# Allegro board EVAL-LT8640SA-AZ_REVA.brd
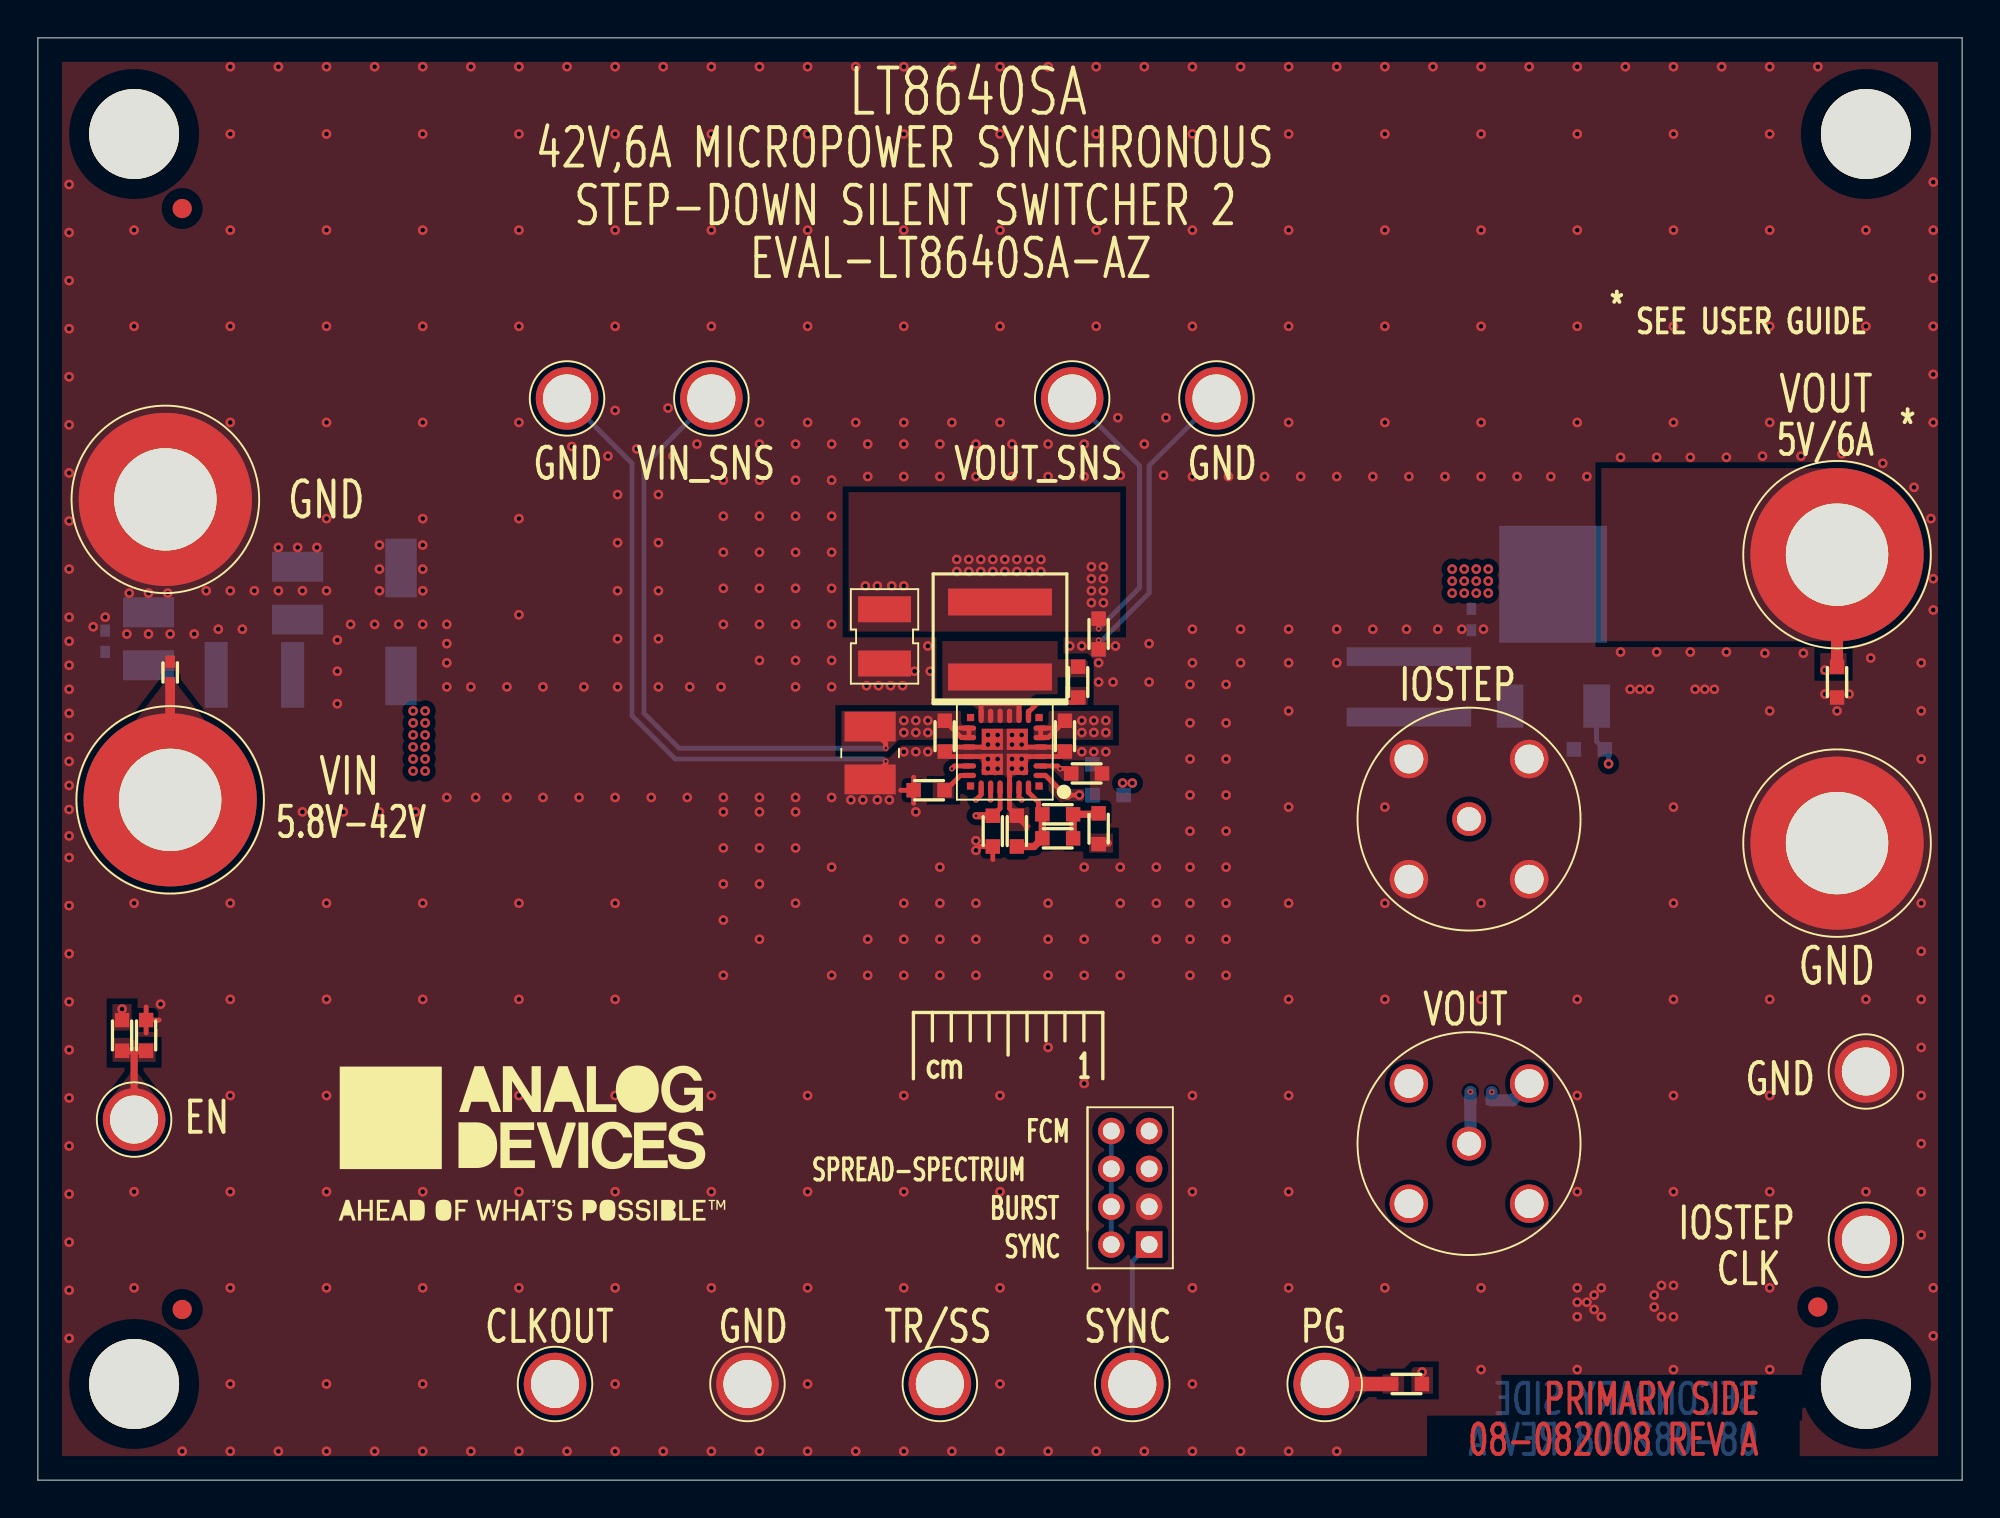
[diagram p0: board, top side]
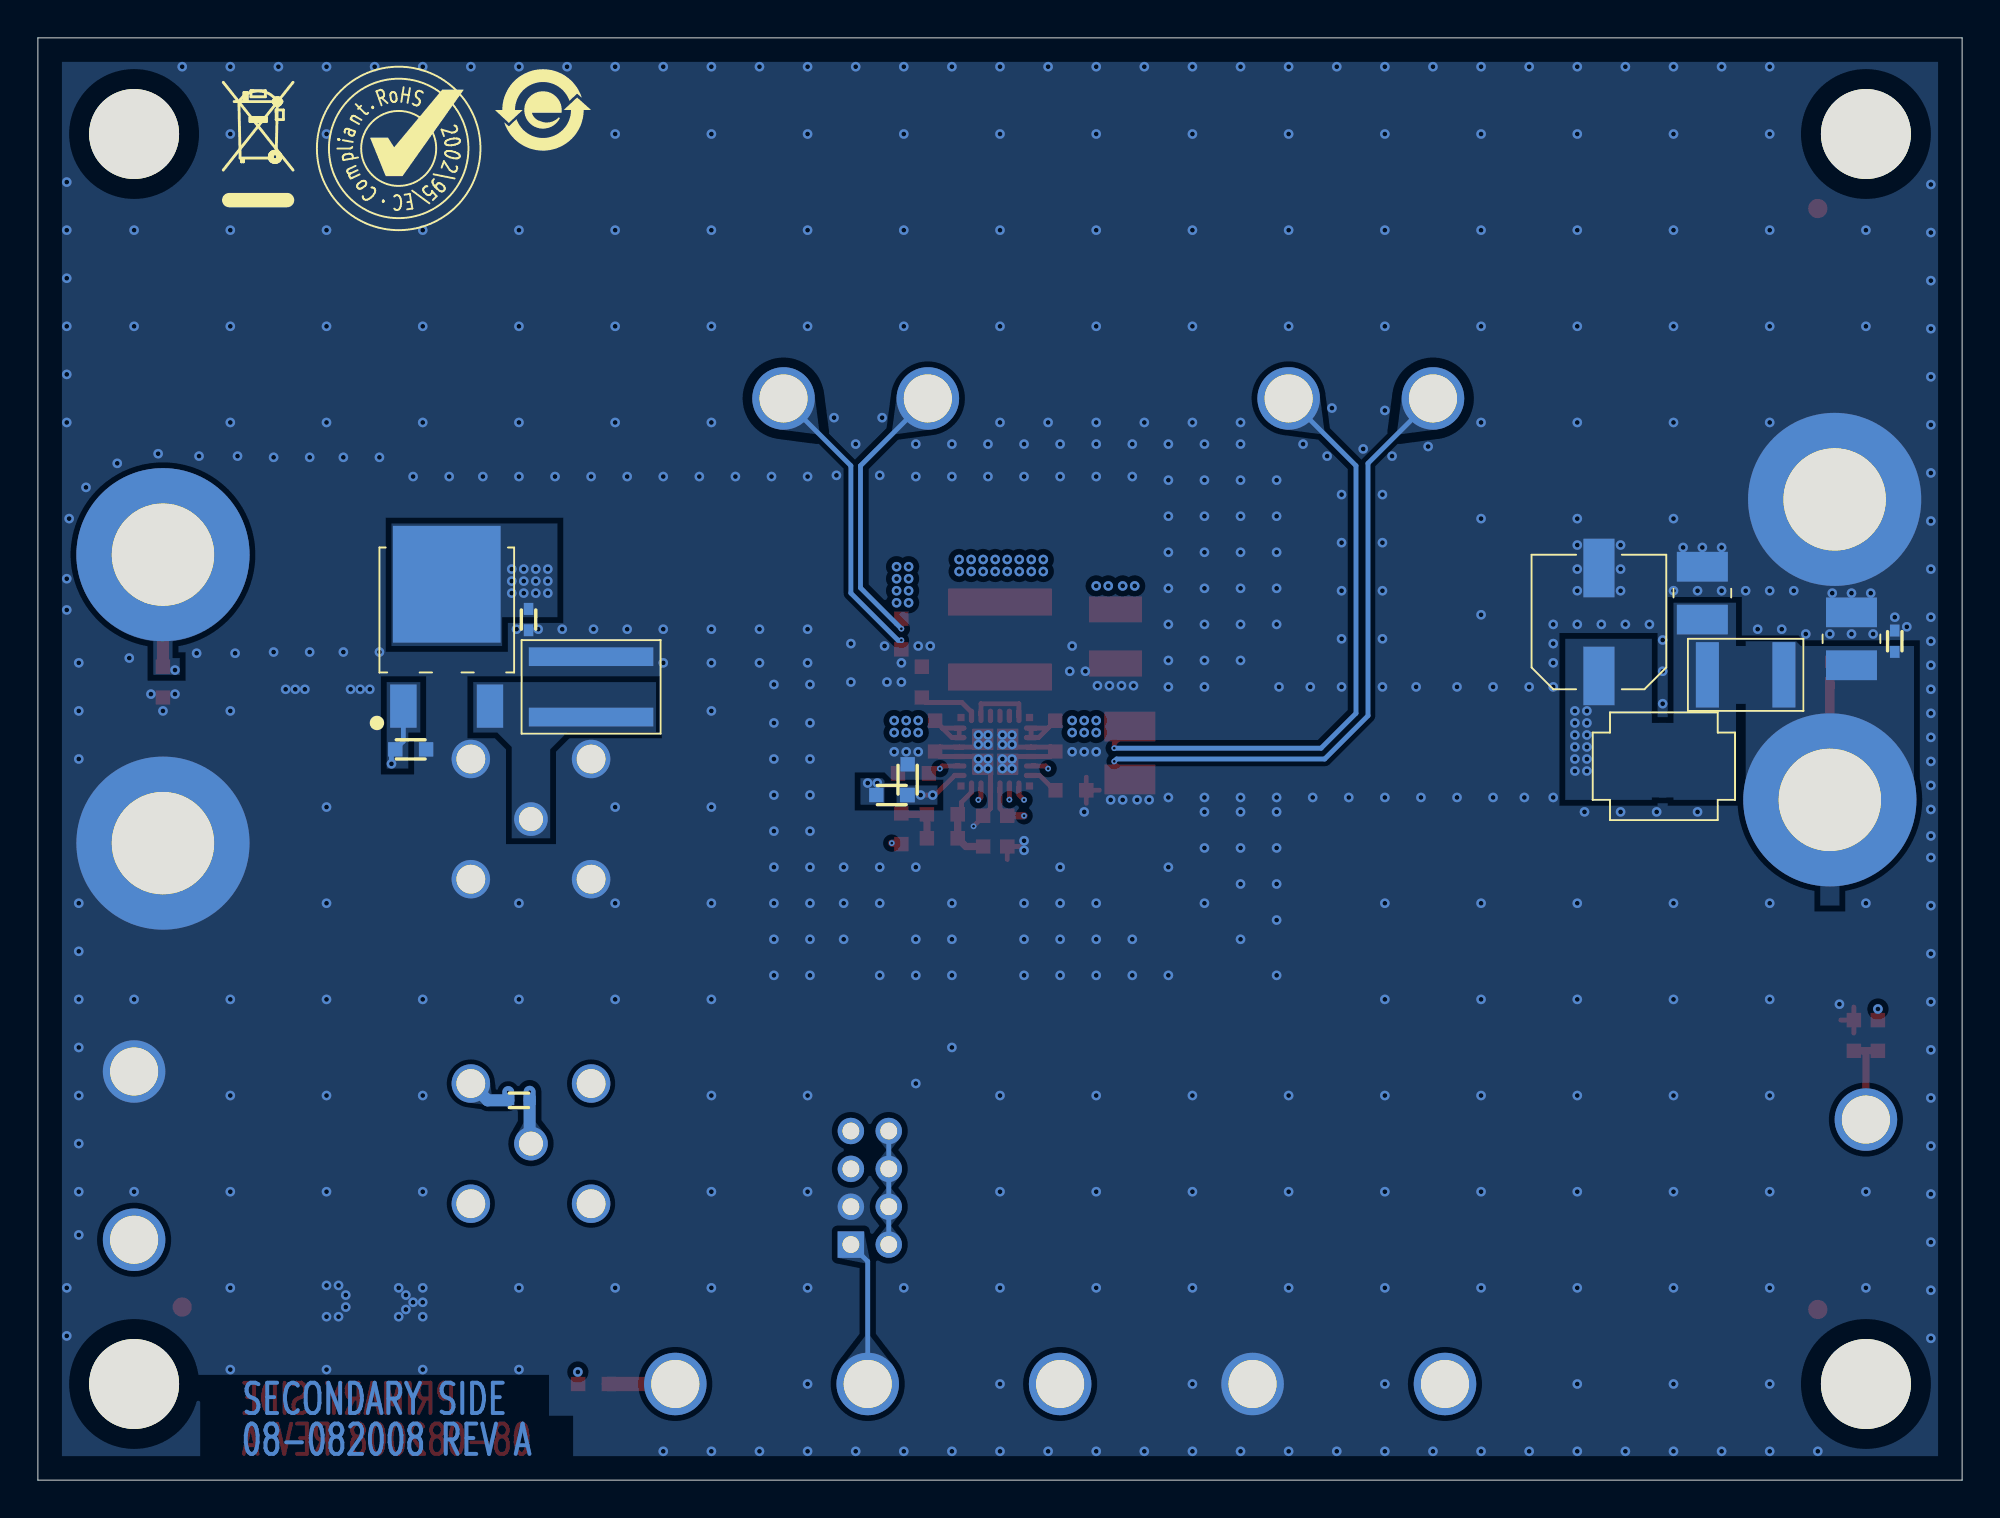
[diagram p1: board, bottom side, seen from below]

Outline 101.6 x 76.2 mm; copper layers: TOP, LAYER_2, LAYER_3, BOTTOM. Coordinates in mm from the lower left corner of the outline.
Outline path: 0,76.2 0,0 101.6,0 101.6,76.2 0,76.2

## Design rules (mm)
constraint set DEFAULT: min track width 0.254

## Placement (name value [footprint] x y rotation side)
C1  22UF  [CPLSMSQ260H315]  19.18 45.34 90 bottom
C2  10uF  [C1210-2]  43.94 38.42 270 top
C3  1uF  [C0603]  47.88 39.31 270 top
C4  1uF  [C0603]  54.23 39.31 270 top
C5  0.1uF  [C0603]  50.42 34.29 270 top
C6  10pF  [C0603]  53.85 33.91 180 top
C7  100UF  [C1210H110]  44.7 44.58 270 top
C8  1uF  [C0603]  56.01 44.7 270 top
C9  10uF  [C0603]  95 42.16 270 top
C10  10uF  [C1210-2]  13.72 46.86 90 bottom
C11  10uF  [C1210-2]  5.84 44.45 90 bottom
C12  0.1uF  [C0402H22]  6.99 42.67 90 top
C13  0.1uF  [C0402H22]  3.56 44.32 90 bottom
C14  TBD0603  [C0603]  55.68 37.01 90 bottom
C15  TBD0603  [C0603]  54.93 42.16 90 top
C16  TBD0603  [C0603]  55.37 37.34 0 top
C17  1uF  [C0402]  76.2 20.07 0 bottom
C18  1uF  [C0402]  75.69 45.47 270 bottom
FB1  100OHM AT 100MEGHZ  [L1812H100]  11.43 42.55 0 bottom
J1  575-4  [CNBANANAD312LD203]  6.99 35.94 0 top
J2  575-4  [CNBANANAD312LD203]  6.73 51.82 0 top
J3  575-4  [CNBANANAD312LD203]  95 48.9 0 top
J4  575-4  [CNBANANAD312LD203]  95 33.66 0 top
J5  112404  [CNAMPHENOL112404]  75.56 17.78 0 top
J6  112404  [CNAMPHENOL112404]  75.56 34.92 0 top
JP1  62000821121  [CNTHMHDR2X4L315W157H248]  58.67 12.45 90 top
L1  1.5UH  [LSML250W258H126]  50.8 44.45 90 top
NOREF  -  []  154.56 189.99 0 top
NOREF#2  -  [unnamed#2]  96.52 5.08 180 top
NOREF#3  -  []  249.05 252.09 0 top
NOREF#4  -  []  -76.2 -76.2 0 top
NOREF#5  -  []  63.5 63.5 180 top
NOREF#6  -  []  85.09 4.06 270 top
NOREF#7  -  []  -76.2 -76.2 0 top
NOREF#8  -  []  181.23 81.28 0 top
NOREF#9  -  []  324.74 191.64 0 top
NOREF#10  -  []  0 76.2 0 top
NOREF#11  -  []  338.45 117.73 0 top
NOREF#12  -  []  244.35 286 0 top
NOREF#13  -  []  46.23 21.21 0 top
NOREF#14  -  []  -76.2 -76.2 0 top
NOREF#15  -  [unnamed#2]  7.62 9.02 0 top
NOREF#16  -  []  52.7 82.55 0 top
NOREF#17  -  []  25.53 17.78 0 top
NOREF#18  -  [unnamed#2]  5.08 5.08 180 top
NOREF#19  -  [unnamed#2]  7.62 67.18 0 top
NOREF#20  -  [unnamed#2]  93.98 9.14 0 top
NOREF#21  -  []  63.5 0 90 top
NOREF#22  -  []  101.6 0 90 top
NOREF#23  -  []  0 63.5 270 top
NOREF#24  -  []  0 0 0 top
NOREF#25  -  [unnamed#2]  96.52 71.12 180 top
NOREF#26  -  [unnamed#2]  5.08 71.12 180 top
NOREF#27  -  []  90.17 67.31 180 bottom
NOREF#28  -  []  82.55 70.36 180 bottom
NOREF#29  -  []  74.93 72.39 180 bottom
Q1  SUD50N04-8M8P-4GE3  [TO252-3]  80.01 45.09 180 bottom
R1  100K  [R0603]  4.45 23.5 270 top
R2  17.8K  [R0603]  47.05 36.45 180 top
R3  243K  [R0603]  51.69 34.29 90 top
R4  100K  [R0603]  72.26 5.08 180 top
R5  50  [R0603]  56.01 34.42 270 top
R6  1MEG  [R0603]  53.85 35.18 180 top
R7  0  [R0603]  56.52 36.2 0 bottom
R8  TBD0603  [R0603]  5.71 23.5 90 top
R9  0.1  [R1225H28]  72.39 41.91 90 bottom
R10  49.9  [R0603]  81.92 38.61 180 bottom
TP1  2501-2-00-80-00-00-07-0  [CNMILLMAX2501]  96.52 21.59 0 top
TP2  2501-2-00-80-00-00-07-0  [CNMILLMAX2501]  27.94 57.15 0 top
TP3  2501-2-00-80-00-00-07-0  [CNMILLMAX2501]  96.52 12.7 0 top
TP4  2501-2-00-80-00-00-07-0  [CNMILLMAX2501]  57.78 5.08 0 top
TP5  2501-2-00-80-00-00-07-0  [CNMILLMAX2501]  27.3 5.08 0 top
TP6  2501-2-00-80-00-00-07-0  [CNMILLMAX2501]  47.62 5.08 0 top
TP7  2501-2-00-80-00-00-07-0  [CNMILLMAX2501]  67.94 5.08 0 top
TP8  2501-2-00-80-00-00-07-0  [CNMILLMAX2501]  37.47 5.08 0 top
TP9  2501-2-00-80-00-00-07-0  [CNMILLMAX2501]  35.56 57.15 0 top
TP10  2501-2-00-80-00-00-07-0  [CNMILLMAX2501]  5.08 19.05 0 top
TP11  2501-2-00-80-00-00-07-0  [CNMILLMAX2501]  54.61 57.15 0 top
TP12  2501-2-00-80-00-00-07-0  [CNMILLMAX2501]  62.23 57.15 0 top
U1  LT8640SAAV#TRPBF  [QFN24_05-08-1511]  51.05 38.48 90 top

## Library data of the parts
C1 = CAPP: Tolerance: 20; User Part Number: UPN; alternate symbols: (CPLSMSQ260H315); part number: CAPP_SM-22UF,63V,20,E063520,CPLSMSQ260H315; tolerance: 20
C2 = CAP: Tolerance: 10; User Part Number: UPN; alternate symbols: (C1210-2); part number: CAP_SM-10UF,50V,10,E033329,C1210-2; tolerance: 10
C3 C4 = CAP: Tolerance: 10; User Part Number: UPN; alternate symbols: (C0603); part number: CAP_SM-1UF,50V,10,E034666,C0603; tolerance: 10
C5 = CAP: Tolerance: 10; User Part Number: UPN; alternate symbols: (C0603); part number: CAP_SM-0.1UF,16V,10,E011547,C0603; tolerance: 10
C6 = CAP: Tolerance: 5; User Part Number: UPN; alternate symbols: (C0603); part number: CAP_SM-10PF,50V,5,E031564,C0603; tolerance: 5
C7 = CAP: Tolerance: 20; User Part Number: UPN; alternate symbols: (C1210H110); part number: CAP_SM-100UF,10V,20,E063422,C1210H110; tolerance: 20
C8 = CAP: Tolerance: 10; User Part Number: UPN; alternate symbols: (C0603); part number: CAP_SM-1UF,10V,10,E024444,C0603; tolerance: 10
C9 = CAP: Tolerance: 10; User Part Number: UPN; alternate symbols: (C0603); part number: CAP_SM-10UF,10V,10,E020723,C0603; tolerance: 10
C10 C11 = CAP: Tolerance: 10; User Part Number: UPN; alternate symbols: (C1210-2); part number: CAP_SM-10UF,50V,10,E022361,C1210-2; tolerance: 10
C12 C13 = CAP: Tolerance: 10; User Part Number: UPN; alternate symbols: (C0402H22); part number: CAP_SM-0.1UF,50V,10,E018452,C0402H22; tolerance: 10
C14-C16 = CAP: User Part Number: UPN; alternate symbols: (C0603); part number: CAP_SM-TBD0603,TBD0603,TBD0603,E000382,C0603
C17 C18 = CAP: Tolerance: 10; User Part Number: UPN; alternate symbols: (C0402); part number: CAP_SM-1UF,10V,10,E017585,C0402; tolerance: 10
FB1 = FERRITE: User Part Number: UPN; Tolerance: 25; alternate symbols: (L1812H100); part number: FERRITE_SM-100OHM AT 100MEGHZ,25,E032797,L1812H100; tolerance: 25
J1-J4 = CNTP1P: Tolerance: N/A; User Part Number: UPN; alternate symbols: (CNBANANAD312LD203); part number: CNTP1P_TH-575-4,E012555,CNBANANAD312LD203; tolerance: N/A
J5 J6 = CNBNC5P: Tolerance: N/A; User Part Number: UPN; alternate symbols: (CNAMPHENOL112404); part number: CNBNC5P_TH-112404,E020078,CNAMPHENOL112404; tolerance: N/A
JP1 = CN8P_ODD_EVEN: User Part Number: UPN; Tolerance: N/A; alternate symbols: (CNTHMHDR2X4L315W157H248); part number: CN8P_ODD_EVEN_TH-62000821121,E048747,CNTHMHDR2X4L315W157H248; tolerance: N/A
L1 = IND: User Part Number: UPN; Tolerance: 20; alternate symbols: (LSML250W258H126); part number: IND_SM-1.5UH,20,E047799,LSML250W258H126; tolerance: 20
Q1 = TRANNMOSFET_V8: Tolerance: N/A; User Part Number: UPN; alternate symbols: (TO252-3); part number: TRANNMOSFET_V8_SM-SUD50N04-8M8P-4GE3,E027839,TO252-3; tolerance: N/A
R1 R4 = RES: Tolerance: 1; User Part Number: UPN; alternate symbols: (R0603); part number: RES_SM-100K,E030871,1/10W,1,R0603; tolerance: 1
R2 = RES: Tolerance: 1; User Part Number: UPN; alternate symbols: (R0603); part number: RES_SM-17.8K,E044268,1/10W,1,R0603; tolerance: 1
R3 = RES: Tolerance: 1; User Part Number: UPN; alternate symbols: (R0603); part number: RES_SM-243K,E029637,1/10W,1,R0603; tolerance: 1
R5 = RES: Tolerance: 1; User Part Number: UPN; alternate symbols: (R0603); part number: RES_SM-50,E017801,1/10W,1,R0603; tolerance: 1
R6 = RES: Tolerance: 1; User Part Number: UPN; alternate symbols: (R0603); part number: RES_SM-1MEG,E030873,1/10W,1,R0603; tolerance: 1
R7 = RES: Tolerance: JUMPER; User Part Number: UPN; alternate symbols: (R0603); part number: RES_SM-0,E006826,1/10W,JUMPER,R0603; tolerance: JUMPER
R8 = RES: User Part Number: UPN; alternate symbols: (R0603); part number: RES_SM-TBD0603,E004050,TBD0603,TBD0603,R0603
R9 = RES: User Part Number: UPN; Tolerance: 1; alternate symbols: (R1225H28); part number: RES_SM-0.1,E066497,3W,1,R1225H28; tolerance: 1
R10 = RES: Tolerance: 1; User Part Number: UPN; alternate symbols: (R0603); part number: RES_SM-49.9,E003673,1/10W,1,R0603; tolerance: 1
TP1-TP12 = CNTP1P: User Part Number: UPN; Tolerance: N/A; alternate symbols: (CNMILLMAX2501); part number: CNTP1P_TH-2501-2-00-80-00-00-07-0,E031108,CNMILLMAX2501; tolerance: N/A
U1 = ADLT8640SA: Tolerance: N/A; User Part Number: UPN; alternate symbols: (QFN24_05-08-1511); part number: ADLT8640SA_SM-LT8640SAAV#TRPBF,E065895,QFN24_05-08-1511; tolerance: N/A

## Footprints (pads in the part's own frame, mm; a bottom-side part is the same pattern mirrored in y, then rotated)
C0402
  rect 0.635x0.508 smd: 1(-0.564,0) 2(0.564,0)
C0402H22
  rect 0.635x0.508 smd: 1(-0.564,0) 2(0.564,0)
C0603
  rect 0.762x0.762 smd: 1(-0.813,0) 2(0.813,0)
C1210-2
  rect 1.575x2.692 smd: 1(-1.397,0) 2(1.397,0)
C1210H110
  rect 1.372x2.794 smd: 1(-1.431,0) 2(1.431,0)
CNAMPHENOL112404
  round 1.778 hole 1.27: 1(0,0)
  round 2.032 hole 1.524: 2(-3.175,3.175) 3(3.175,3.175) 4(3.175,-3.175) 5(-3.175,-3.175)
CNBANANAD312LD203
  round 9.144 hole 5.41: 1(0,0)
CNMILLMAX2501
  round 3.302 hole 2.54: 1(0,0)
CNTHMHDR2X4L315W157H248
  rect 1.397x1.397 hole 0.889: 1(0,0)
  round 1.397 hole 0.889: 2(0,2) 3(2,0) 4(2,2) 5(4,0) 6(4,2) 7(6,0) 8(6,2)
CPLSMSQ260H315
  rect 3.099x1.651 smd: N(2.85,0) P(-2.85,0)
L1812H100
  rect 1.219x3.454 smd: 1(-2.02,0) 2(2.02,0)
LSML250W258H126
  rect 1.422x5.486 smd: 1(-2.019,0) 2(1.943,0)
QFN24_05-08-1511
  rect 0.381x0.381 smd: (-1.809,1.809) (-1.809,-1.809) (1.809,1.809) (1.809,-1.809)
  oval 0.279x0.762 smd: 1(-1.25,-1.896) 2(-0.75,-1.896) 3(-0.25,-1.896) 4(0.25,-1.896) 5(0.75,-1.896) 6(1.25,-1.896) 13(1.25,1.896) 14(0.75,1.896) 15(0.25,1.896) 16(-0.25,1.896) 17(-0.75,1.896) 18(-1.25,1.896)
  oval 0.762x0.279 smd: 7(1.896,-1.25) 8(1.896,-0.75) 9(1.896,-0.25) 10(1.896,0.25) 11(1.896,0.75) 12(1.896,1.25) 19(-1.896,1.25) 20(-1.896,0.75) 21(-1.896,0.25) 22(-1.896,-0.25) 23(-1.896,-0.75) 24(-1.896,-1.25)
  rect 1.118x1.118 smd: 25(-0.659,-0.659) 26(-0.659,0.659) 27(0.659,-0.659) 28(0.659,0.659)
R0603
  rect 0.762x0.762 smd: 1(-0.813,0) 2(0.813,0)
R1225H28
  rect 0.991x6.579 smd: 1(-1.595,0) 2(1.595,0)
TO252-3
  rect 1.397x2.286 smd: 1(-2.29,-4.191) 2(2.28,-4.191)
  rect 5.69x6.172 smd: 3(0,2.248)
unnamed#2
  round 4.75 hole 4.75 unplated: (0,0)

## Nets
GROUND: C1.N(N2) C2.2(N2) C3.2(N2) C4.2(N2) C5.2(N2) C7.2(N2) C8.2(N2) C9.2(N2) C10.2(N2) C11.2(N2) C12.2(N2) C13.2(N2) C14.2(N2) C16.2(N2) C17.2(N2) C18.2(N2) J2.1(N1) J4.1(N1) J5.2 J5.3 J5.4 J5.5(SH4) J6.2 J6.3 J6.4 J6.5(SH4) JP1.3 R2.2(N2) R3.2(N2) R8.2(N2) R9.2(N2) R10.2(N2) TP1.1(N1) TP2.1(N1) TP8.1(N1) TP12.1(N1) U1.3 U1.4 U1.15 U1.16 U1.22 U1.25 U1.26 U1.27 U1.28
UNNAMED_2_ADLT8640SA_I41_BIAS: C14.1 R7.1 U1.1
UNNAMED_2_ADLT8640SA_I41_BST: C15.1 U1.7
UNNAMED_2_ADLT8640SA_I41_CLKOUT: TP5.1(N1) U1.19
UNNAMED_2_ADLT8640SA_I41_FB: C6.2(N2) R3.1 R6.2(N2) U1.24
UNNAMED_2_ADLT8640SA_I41_PG: R4.2(N2) TP7.1(N1) U1.23
UNNAMED_2_ADLT8640SA_I41_RT: R2.1 U1.18
UNNAMED_2_ADLT8640SA_I41_SW1: C15.2(N2) L1.1 U1.8 U1.9 U1.10 U1.11 U1.12
UNNAMED_2_ADLT8640SA_I41_SYNC: JP1.2 JP1.4 JP1.6 JP1.8(N8) U1.20
UNNAMED_2_ADLT8640SA_I41_TR: C5.1 TP6.1(N1) U1.21
UNNAMED_2_ADLT8640SA_I41_VIN1: C1.P C2.1 C3.1 C4.1 C10.1 C11.1 C12.1 C13.1 FB1.1 FB1.2(N2) J1.1(N1) R1.1 TP9.1(N1) U1.5 U1.6 U1.13 U1.14(VIN_4)
UNNAMED_2_CAP_I33_N1: C6.1 R5.1 R6.1
UNNAMED_2_CN8PODDEVEN_I14_N1: JP1.1 TP4.1(N1)
UNNAMED_2_CN8PODDEVEN_I14_N5: C16.1 JP1.5 U1.2
UNNAMED_2_CNBNC5P_I96_CNTR: J6.1 Q1.2(S) R9.1
UNNAMED_2_CNTP1P_I81_N1: Q1.1 R10.1 TP3.1(N1)
UNNAMED_2_RES_I25_N2: R1.2(N2) R8.1 TP10.1(N1) U1.17
VOUT: C7.1 C8.1 C9.1 C17.1 C18.1 J3.1(N1) J5.1 L1.2(N2) Q1.3 R4.1 R5.2(N2) R7.2(N2) TP11.1(N1)

Pads without a net: JP1 7

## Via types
v1: diameter 0.508, hole 0.254, TOP to BOTTOM, 632 vias
v2: diameter 0.305, hole 0.152, TOP to BOTTOM, 14 vias

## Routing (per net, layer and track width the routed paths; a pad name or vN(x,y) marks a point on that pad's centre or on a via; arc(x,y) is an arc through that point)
GROUND: length 108.1
  TOP w0.254: 49.73,33.48 C5.2 50.42,32.79 ; v2(52.2,34.54) 51.69,35.05 R3.2 51.3,35.49 U1.22 51.3,37.41 U1.25 52.12,38.23 U1.3 53.97,38.23 C4.2 53.99,38.73 U1.4 52.12,38.73 U1.27 ; C8.2 v2(56.01,44.37) ; 46.24,35.76 R2.2 ; R2.2 46.24,37.14 ; R2.2 45.55,36.45 ; 5.71,23.62 R8.2 ; R8.2 6.4,24.31 ; R8.2 5.71,24.99 ; U1.28 49.99,38.73 U1.15 48.12,38.73 C3.2 48.14,38.23 U1.16 49.99,38.23 U1.26 ; v2(44.77,37.97) 44.77,37.85 C2.2
  LAYER_3 w0.254: v1(94.36,41.53) 93.93,41.96 91.36,41.96 89.28,39.88 82.3,39.88 81.03,38.61 81.03,27.3 76.45,22.73 76.45,20.81 v2(76.76,20.5)
  BOTTOM w0.254: v2(56.01,44.37) 56.18,44.37 58.67,46.86 58.67,53.59 TP12.1 ; TP2.1 31.37,53.72 31.37,40.39 33.66,38.1 44.64,38.1 v2(44.77,37.97)
  BOTTOM w0.635: v2(76.76,20.5) C17.2 77.85,20.07 J5.3
  vias: v1(1.65,68.45) v1(1.65,65.91) v1(1.65,63.37) v1(1.65,60.83) v1(1.65,58.29) v1(1.65,55.75) v1(1.65,53.21) v1(1.65,50.67) v1(1.65,48.13) v1(1.65,45.59) v1(1.65,44.32) v1(1.65,43.05) v1(1.65,41.78) v1(1.65,40.51) v1(1.65,39.24) v1(1.65,37.97) v1(1.65,36.7) v1(1.65,35.43) v1(1.65,34.04) v1(1.65,32.89) v1(1.65,30.35) v1(1.65,27.81) v1(1.65,25.27) v1(1.65,22.73) v1(1.65,20.19) v1(1.65,17.65) v1(1.65,15.11) v1(1.65,12.57) v1(1.65,10.03) v1(1.65,7.49) v1(2.92,45.09) v1(3.56,45.59) v1(4.7,44.7) v1(4.83,46.86) v1(5.08,66.04) v1(5.08,60.96) v1(5.08,30.48) v1(5.08,15.24) v1(5.08,10.16) v1(5.84,46.86) v1(5.84,44.7) v1(6.48,25.15) v1(6.86,46.86) v1(6.99,44.7) v1(7.62,1.52) v1(8.26,44.7) v1(8.89,46.99) v1(9.53,44.96) v1(10.16,74.68) v1(10.16,71.12) v1(10.16,66.04) v1(10.16,60.96) v1(10.16,55.88) v1(10.16,46.99) v1(10.16,30.48) v1(10.16,25.4) v1(10.16,20.32) v1(10.16,15.24) v1(10.16,10.16) v1(10.16,5.08) v1(10.16,1.52) v1(10.79,44.96) v1(11.43,46.99) v1(12.7,74.68) v1(12.7,49.28) v1(12.7,46.99) v1(12.7,1.52) v1(13.72,49.28) v1(13.97,46.99) v1(13.97,35.31) v1(14.73,49.28) v1(15.24,74.68) v1(15.24,71.12) v1(15.24,66.04) v1(15.24,60.96) v1(15.24,55.88) v1(15.24,50.8) v1(15.24,46.99) v1(15.24,30.48) v1(15.24,25.4) v1(15.24,20.32) v1(15.24,15.24) v1(15.24,10.16) v1(15.24,5.08) v1(15.24,1.52) v1(15.81,44.39) v1(15.81,42.74) v1(15.81,41.02) v1(16.13,35.31) v1(16.51,45.21) v1(17.78,74.68) v1(17.78,45.21) v1(17.78,1.52) v1(18.03,49.4) v1(18.03,48.13) v1(18.03,46.99) v1(18.03,35.31) v1(19.05,45.21) v1(19.94,35.31) v1(20.32,74.68) v1(20.32,71.12) v1(20.32,66.04) v1(20.32,60.96) v1(20.32,55.88) v1(20.32,50.8) v1(20.32,49.4) v1(20.32,48.13) v1(20.32,46.99) v1(20.32,45.21) v1(20.32,30.48) v1(20.32,25.4) v1(20.32,20.32) v1(20.32,15.24) v1(20.32,10.16) v1(20.32,5.08) v1(20.32,1.52) v1(21.59,45.21) v1(21.59,44.2) v1(21.59,43.18) v1(21.59,41.91) v1(21.59,36.07) v1(22.86,74.68) v1(22.86,41.91) v1(22.86,1.52) v1(23.11,36.07) v1(24.77,41.91) v1(24.77,36.07) v1(25.4,74.68) v1(25.4,71.12) v1(25.4,66.04) v1(25.4,60.96) v1(25.4,55.88) v1(25.4,50.8) v1(25.4,45.72) v1(25.4,30.48) v1(25.4,25.4) v1(25.4,20.32) v1(25.4,15.24) v1(25.4,10.16) v1(25.4,1.52) v1(26.67,41.91) v1(26.67,36.07) v1(27.94,74.68) v1(27.94,1.52) v1(28.19,54.61) v1(28.57,36.07) v1(28.83,41.91) v1(30.1,54.1) v1(30.48,74.68) v1(30.48,71.12) v1(30.48,66.04) v1(30.48,60.96) v1(30.48,56.52) v1(30.48,36.07) v1(30.48,30.48) v1(30.48,25.4) v1(30.48,20.32) v1(30.48,15.24) v1(30.48,10.16) v1(30.48,5.08) v1(30.48,1.52) v1(30.61,52.07) v1(30.61,49.53) v1(30.61,46.99) v1(30.61,44.45) v1(30.61,41.91) v1(31.62,54.48) v1(32.38,36.07) v1(32.77,52.07) v1(32.77,49.53) v1(32.77,46.99) v1(32.77,44.45) v1(32.77,41.91) v1(33.02,74.68) v1(33.02,1.52) v1(33.27,56.64) v1(33.53,54.1) v1(34.29,36.07) v1(34.42,41.91) v1(34.8,54.74) v1(35.56,74.68) v1(35.56,71.12) v1(35.56,66.04) v1(35.56,60.96) v1(35.56,20.32) v1(35.56,15.24) v1(35.56,10.16) v1(35.56,1.52) v1(36.07,41.91) v1(36.2,52.83) v1(36.2,50.93) v1(36.2,49.02) v1(36.2,47.12) v1(36.2,45.21) v1(36.2,36.07) v1(36.2,35.31) v1(36.2,33.4) v1(36.2,31.5) v1(36.2,29.59) v1(36.2,26.67) v1(38.1,74.68) v1(38.1,55.88) v1(38.1,54.74) v1(38.1,52.83) v1(38.1,50.93) v1(38.1,49.02) v1(38.1,47.12) v1(38.1,45.21) v1(38.1,43.31) v1(38.1,36.07) v1(38.1,35.31) v1(38.1,33.4) v1(38.1,31.5) v1(38.1,28.57) v1(38.1,1.52) v1(40.01,54.74) v1(40.01,52.83) v1(40.01,50.93) v1(40.01,49.02) v1(40.01,47.12) v1(40.01,45.21) v1(40.01,43.31) v1(40.01,41.91) v1(40.01,36.07) v1(40.01,35.31) v1(40.01,33.4) v1(40.01,30.48) v1(40.64,74.68) v1(40.64,71.12) v1(40.64,66.04) v1(40.64,60.96) v1(40.64,55.88) v1(40.64,20.32) v1(40.64,15.24) v1(40.64,10.16) v1(40.64,5.08) v1(40.64,1.52) v1(41.91,54.74) v1(41.91,52.83) v1(41.91,50.93) v1(41.91,49.02) v1(41.91,47.12) v1(41.91,45.21) v1(41.91,43.31) v1(41.91,41.91) v1(41.91,36.07) v1(41.91,32.38) v1(41.91,26.67) v1(42.93,35.94) v1(43.18,74.68) v1(43.18,55.88) v1(43.18,1.52) v1(43.56,35.94) v1(43.81,54.74) v1(43.81,53.02) v1(43.75,41.97) v1(43.81,28.57) v1(43.81,26.67) v1(44.32,35.94) v1(44.39,41.97) v1(45.02,41.97) v1(44.96,35.94) v1(45.72,74.68) v1(45.72,71.12) v1(45.72,66.04) v1(45.72,60.96) v1(45.72,55.88) v1(45.72,54.74) v1(45.72,53.02) v1(45.66,41.97) v1(45.72,38.48) v1(45.72,30.48) v1(45.72,28.57) v1(45.72,26.67) v1(45.72,20.32) v1(45.72,15.24) v1(45.72,10.16) v1(45.72,1.52) v1(46.29,42.74) v1(46.35,38.48) v1(46.35,35.31) v1(46.99,44.07) v1(46.99,38.48) v1(47.12,42.74) v1(47.62,54.74) v1(47.62,53.02) v1(47.62,32.38) v1(47.62,30.48) v1(47.62,28.57) v1(47.62,26.67) v1(48.26,74.68) v1(48.26,55.88) v1(48.26,1.52) v1(49.53,54.74) v1(49.53,53.02) v1(49.53,33.78) v1(49.53,33.27) v1(49.53,30.48) v1(49.53,28.57) v1(49.53,26.67) v1(50.16,39.37) v1(50.16,38.86) v1(50.16,38.1) v1(50.16,37.59) v1(50.67,39.37) v1(50.67,38.86) v1(50.67,38.1) v1(50.67,37.59) v1(50.8,74.68) v1(50.8,71.12) v1(50.8,66.04) v1(50.8,60.96) v1(50.8,55.88) v1(50.8,20.32) v1(50.8,15.24) v1(50.8,10.16) v1(50.8,5.08) v1(50.8,1.52) v1(51.44,54.74) v1(51.44,53.02) v1(51.44,39.37) v1(51.44,38.86) v1(51.44,38.1) v1(51.44,37.59) v1(51.94,39.37) v1(51.94,38.86) v1(51.94,38.1) v1(51.94,37.59) v1(53.34,74.68) v1(53.34,54.74) v1(53.34,53.02) v1(53.34,30.48) v1(53.34,28.57) v1(53.34,26.67) v1(53.34,22.86) v1(53.34,1.52) v1(54.48,44.07) v1(55.12,44.07) v1(55.12,38.48) v1(55.24,54.74) v1(55.24,53.02) v1(55.24,32.38) v1(55.24,28.57) v1(55.24,26.67) v1(55.24,20.95) v1(55.75,38.48) v1(55.88,74.68) v1(55.88,71.12) v1(55.88,66.04) v1(55.88,60.96) v1(55.88,10.16) v1(55.88,1.52) v1(56.01,43.18) v1(56.01,42.16) v1(56.39,38.48) v1(56.77,42.16) v1(56.9,44.07) v1(57.02,56.13) v1(57.15,53.09) v1(57.15,32.38) v1(57.15,30.48) v1(57.15,26.67) v1(58.42,74.68) v1(58.42,54.74) v1(58.42,1.52) v1(58.67,44.2) v1(58.67,42.16) v1(59.05,32.38) v1(59.05,30.48) v1(59.05,28.57) v1(59.44,53.09) v1(59.56,56.13) v1(60.83,42.04) v1(60.83,40.01) v1(60.83,38.1) v1(60.83,36.2) v1(60.83,34.29) v1(60.83,32.38) v1(60.83,30.48) v1(60.83,28.57) v1(60.83,26.67) v1(60.96,74.68) v1(60.96,71.12) v1(60.96,66.04) v1(60.96,60.96) v1(60.96,53.02) v1(60.96,44.96) v1(60.96,43.18) v1(60.96,20.32) v1(60.96,15.24) v1(60.96,10.16) v1(60.96,5.08) v1(60.96,1.52) v1(62.74,42.04) v1(62.74,40.01) v1(62.74,38.1) v1(62.74,36.2) v1(62.74,34.29) v1(62.74,32.38) v1(62.74,30.48) v1(62.74,28.57) v1(62.74,26.67) v1(62.87,53.02) v1(63.5,74.68) v1(63.5,44.96) v1(63.5,43.18) v1(63.5,1.52) v1(64.77,53.02) v1(66.04,74.68) v1(66.04,71.12) v1(66.04,66.04) v1(66.04,60.96) v1(66.04,55.88) v1(66.04,44.96) v1(66.04,43.18) v1(66.04,40.64) v1(66.04,35.56) v1(66.04,30.48) v1(66.04,25.4) v1(66.04,20.32) v1(66.04,15.24) v1(66.04,10.16) v1(66.04,1.52) v1(66.67,53.02) v1(68.58,74.68) v1(68.58,53.02) v1(68.58,44.96) v1(68.58,43.18) v1(68.58,1.52) v1(70.48,53.02) v1(70.48,44.96) v1(71.12,74.68) v1(71.12,71.12) v1(71.12,66.04) v1(71.12,60.96) v1(71.12,55.88) v1(71.12,35.56) v1(71.12,30.48) v1(71.12,25.4) v1(71.12,10.16) v1(72.26,44.96) v1(72.39,53.02) v1(73.66,74.68) v1(73.91,44.96) v1(74.3,53.02) v1(75.18,44.96) v1(76.2,74.68) v1(76.2,71.12) v1(76.2,66.04) v1(76.2,60.96) v1(76.2,55.88) v1(76.2,53.02) v1(76.2,30.48) v1(76.2,25.4) v1(76.2,10.16) v1(76.2,5.84) v1(76.33,44.96) v1(78.11,53.02) v1(78.74,74.68) v1(79.88,53.02) v1(81.28,74.68) v1(81.28,71.12) v1(81.28,66.04) v1(81.28,60.96) v1(81.28,55.88) v1(81.28,25.4) v1(81.28,20.32) v1(81.28,15.24) v1(81.28,10.16) v1(81.28,9.4) v1(81.28,8.64) v1(81.28,5.84) v1(81.79,53.02) v1(81.79,9.4) v1(82.17,9.78) v1(82.17,9.02) v1(82.55,10.16) v1(82.55,8.64) v1(83.57,54.04) v1(83.57,43.75) v1(83.82,74.68) v1(84.07,41.78) v1(84.58,41.78) v1(85.09,41.78) v1(85.34,9.78) v1(85.34,9.14) v1(85.47,54.04) v1(85.47,43.75) v1(85.72,10.29) v1(85.72,8.64) v1(86.36,74.68) v1(86.36,71.12) v1(86.36,66.04) v1(86.36,60.96) v1(86.36,55.88) v1(86.36,35.56) v1(86.36,30.48) v1(86.36,25.4) v1(86.36,20.32) v1(86.36,15.24) v1(86.36,10.29) v1(86.36,8.64) v1(86.36,5.84) v1(87.25,54.04) v1(87.25,43.75) v1(87.5,41.78) v1(88.01,41.78) v1(88.52,41.78) v1(88.9,74.68) v1(89.15,54.04) v1(89.15,43.75) v1(91.06,54.1) v1(91.19,43.69) v1(91.44,74.68) v1(91.44,71.12) v1(91.44,66.04) v1(91.44,60.96) v1(91.44,55.88) v1(91.44,40.64) v1(91.44,25.4) v1(91.44,20.32) v1(91.44,15.24) v1(91.44,10.16) v1(91.44,5.84) v1(93.09,54.1) v1(93.22,43.69) v1(93.98,74.68) v1(95,40.64) v1(95.25,54.23) v1(95.63,41.53) v1(96.52,66.04) v1(96.52,60.96) v1(96.52,25.4) v1(96.52,15.24) v1(96.77,43.43) v1(97.41,53.72) v1(99.06,52.45) v1(99.44,43.18) v1(99.44,40.64) v1(99.44,38.1) v1(99.44,30.48) v1(99.44,27.94) v1(99.44,25.4) v1(99.44,22.86) v1(99.44,20.32) v1(99.44,17.78) v1(99.44,15.24) v1(99.44,12.95) v1(99.95,50.8) v1(100.08,68.58) v1(100.08,66.04) v1(100.08,63.5) v1(100.08,60.96) v1(100.08,58.42) v1(100.08,55.88) v1(100.08,47.62) v1(100.08,45.97) v1(100.08,10.16) v1(100.08,7.62)
UNNAMED_2_ADLT8640SA_I41_BIAS: length 2.5
  TOP w0.254: v1(54.99,36.2) v1(54.36,36.2) 54.23,36.2 53.19,37.23 U1.1
UNNAMED_2_ADLT8640SA_I41_BST: length 3.2
  TOP w0.254: U1.7 52.3,40.58 52.81,41.08 54.72,41.08 54.93,41.29 C15.1
UNNAMED_2_ADLT8640SA_I41_CLKOUT: length 41.4
  TOP w0.254: U1.19 49.8,36.22 v2(49.53,35.94)
  LAYER_3 w0.254: v2(49.53,35.94) 48.51,35.94 27.3,14.73 TP5.1
UNNAMED_2_ADLT8640SA_I41_FB: length 4.5
  TOP w0.254: R6.2 52.83,35.38 52.83,35.81 52.3,36.34 U1.24
  TOP w0.381: R3.1 52.6,33.48 C6.2 R6.2
UNNAMED_2_ADLT8640SA_I41_PG: length 41.7
  TOP w0.254: v2(51.94,35.94) 51.8,36.08 U1.23
  TOP w0.762: TP7.1 R4.2
  LAYER_3 w0.254: TP7.1 63.5,9.53 63.5,21.59 52.96,32.13 52.96,34.92 v2(51.94,35.94)
UNNAMED_2_ADLT8640SA_I41_RT: length 1.6
  TOP w0.254: R2.1 47.93,36.45 48.71,37.23 U1.18
UNNAMED_2_ADLT8640SA_I41_SW1: length 3.3
  TOP w0.254: U1.8 51.8,41.02 49.8,41.02 U1.12
UNNAMED_2_ADLT8640SA_I41_SYNC: length 26.8
  TOP w0.254: U1.20 v2(50.3,35.95)
  LAYER_3 w0.254: v2(50.3,35.95) 50.3,24.82 JP1.8
  BOTTOM w0.254: JP1.8 JP1.6 JP1.4 JP1.2
UNNAMED_2_ADLT8640SA_I41_TR: length 33.3
  TOP w0.254: C5.1 50.8,35.49 U1.21
  TOP w0.381: C5.1 v2(49.53,35.1)
  LAYER_3 w0.254: v2(49.53,35.1) 48.64,34.21 48.64,17.14 47.62,16.13 TP6.1
UNNAMED_2_ADLT8640SA_I41_VIN1: length 57.5
  TOP w0.254: 48.27,39.73 U1.13 U1.14 48.77,39.23 48.27,39.73 ; 48.27,39.73 C3.1 ; 53.84,39.73 53.34,39.23 U1.5 U1.6 53.84,39.73 ; 53.84,39.73 C4.1 ; v2(44.77,38.67) 44.77,38.93 43.94,39.75 C2.1
  TOP w0.508: C12.1 J1.1
  LAYER_3 w0.381: v1(4.45,24.89) 6.99,27.43 J1.1
  BOTTOM w0.254: TP9.1 32,53.59 32,40.51 33.85,38.67 v2(44.77,38.67)
  vias: v1(19.81,40.64) v1(19.81,40.01) v1(19.81,39.37) v1(19.81,38.73) v1(19.81,38.1) v1(19.81,37.47) v1(20.45,40.64) v1(20.45,40.01) v1(20.45,39.37) v1(20.45,38.73) v1(20.45,38.1) v1(20.45,37.47) v1(45.72,40.13) v1(45.72,39.5) v1(46.35,40.13) v1(46.35,39.5) v1(46.99,40.13) v1(46.99,39.5) v1(55.12,40.13) v1(55.12,39.5) v1(55.75,40.13) v1(55.75,39.5) v1(56.39,40.13) v1(56.39,39.5)
UNNAMED_2_CAP_I33_N1: length 2.6
  TOP w0.381: C6.1 R6.1 55.96,35.18 R5.1
UNNAMED_2_CN8PODDEVEN_I14_N1: length 7.7
  BOTTOM w0.254: TP4.1 57.78,11.56 JP1.1
UNNAMED_2_CN8PODDEVEN_I14_N5: length 30
  TOP w0.254: C16.1 54.31,37.59 v2(53.98,37.59) 53.84,37.73 U1.2
  LAYER_3 w0.254: JP1.5 59.82,17.59 59.82,19.3 58.29,20.83 56.64,20.83 51.18,26.29 51.18,36.32 51.69,36.83 53.21,36.83 v2(53.98,37.59)
UNNAMED_2_CNTP1P_I81_N1: length 34.1
  LAYER_3 w0.381: v1(82.93,37.85) 84.07,36.7 84.07,25.15 TP3.1
  BOTTOM w0.254: v1(82.93,37.85) 82.93,38.4 R10.1 82.3,39.04 Q1.1
UNNAMED_2_RES_I25_N2: length 56.7
  TOP w0.254: U1.17 48.4,37.73 v2(48.26,37.59)
  TOP w0.381: 5.08,22.68 TP10.1 ; 5.08,22.68 R1.2 ; 5.08,22.68 R8.1
  LAYER_3 w0.254: TP10.1 27.43,19.05 43.18,34.8 44.83,34.8 47.62,37.59 v2(48.26,37.59)
VOUT: length 153.3
  TOP w0.254: v1(73.09,5.71) 73.08,5.7 R4.1 ; C8.1 v2(56.01,44.98)
  TOP w0.381: R5.2 56.06,33.66 v2(56.52,33.66)
  TOP w0.635: J3.1 C9.1
  LAYER_3 w0.254: v1(94.36,42.8) 93.98,42.42 91.06,42.42 89.03,40.39 82.04,40.39 80.52,38.86 80.52,27.56 75.95,22.99 75.95,20.83 v2(75.64,20.52) ; 94.23,48.9 J3.1 100.2,43.69 100.2,12.45 97.16,9.4 94.49,9.4 91.69,6.6 73.98,6.6 v1(73.09,5.71) ; v2(56.52,33.66) 59.44,36.58 59.44,45.9
  LAYER_3 w0.635: v1(57.28,36.83) v1(57.78,36.83) 57.78,46.1
  BOTTOM w0.254: v2(56.01,44.98) 58.17,47.14 58.17,53.59 TP11.1
  BOTTOM w0.635: J5.1 75.64,17.85 C17.1 v2(75.64,20.52)
  vias: v1(43.69,47.24) v1(44.32,47.24) v1(45.09,47.24) v1(45.72,47.24) v1(48.51,48.64) v1(48.51,48.01) v1(49.15,48.64) v1(49.15,48.01) v1(49.78,48.64) v1(49.78,48.01) v1(50.42,48.64) v1(50.42,48.01) v1(51.05,48.64) v1(51.05,48.01) v1(51.69,48.64) v1(51.69,48.01) v1(52.32,48.64) v1(52.32,48.01) v1(52.96,48.64) v1(52.96,48.01) v1(55.63,48.26) v1(55.63,47.62) v1(55.63,46.99) v1(55.63,46.35) v1(56.26,48.26) v1(56.26,47.62) v1(56.26,46.99) v1(56.26,46.35) v1(74.68,48.13) v1(74.68,47.5) v1(74.68,46.86) v1(75.31,48.13) v1(75.31,47.5) v1(75.31,46.86) v1(75.95,48.13) v1(75.95,47.5) v1(75.95,46.86) v1(76.58,48.13) v1(76.58,47.5) v1(76.58,46.86)

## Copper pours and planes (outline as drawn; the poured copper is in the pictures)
GROUND on TOP: 1.27,74.93 100.33,74.93 100.33,1.27 1.27,1.27 ; 1 cut-out
GROUND on BOTTOM: 1.27,74.93 100.33,74.93 100.33,1.27 1.27,1.27
GROUND on LAYER_2: 1.27,74.93 100.33,74.93 100.33,1.27 1.27,1.27
GROUND on LAYER_3: 1.27,74.93 1.27,1.27 100.33,1.27 100.33,74.93 ; 2 cut-outs
UNNAMED_2_ADLT8640SA_I41_BIAS on TOP: 55.12,35.81 55.24,35.94 55.24,36.51 54.17,36.51 53.34,37.34 53.09,37.34 53.09,37.21 53.34,36.96 53.34,36.45 53.98,35.81
UNNAMED_2_ADLT8640SA_I41_BIAS on BOTTOM: 54.1,36.7 54.1,35.69 56.26,35.69 56.26,36.7
UNNAMED_2_ADLT8640SA_I41_BST on TOP: 55.44,41.91 55.44,40.96 54.23,40.96 54.23,41.91
UNNAMED_2_ADLT8640SA_I41_PG on TOP: 72.14,5.59 72.14,4.57 70.99,4.57 70.99,5.59
UNNAMED_2_ADLT8640SA_I41_RT on TOP: 47.24,36.89 47.24,36 48.39,36 48.39,36.89
UNNAMED_2_ADLT8640SA_I41_SW1 on TOP: 49.66,40.13 49.66,40.64 49.28,41.02 47.75,41.02 47.75,44.32 53.85,44.32 53.85,43.37 55.31,43.37 55.44,43.24 55.44,42.42 53.85,42.42 53.85,41.02 52.2,41.02 51.94,40.77 51.94,40.01 49.78,40.01
UNNAMED_2_ADLT8640SA_I41_VIN1 on TOP: 4.95,25.15 4.95,23.75 3.94,23.75 3.94,25.15
UNNAMED_2_ADLT8640SA_I41_VIN1 on TOP: 52.58,39.12 52.58,39.88 53.09,39.88 53.21,40.01 53.21,40.64 56.77,40.64 56.77,39.12
UNNAMED_2_ADLT8640SA_I41_VIN1 on TOP: 49.53,39.12 49.53,39.88 49.02,39.88 48.9,40.01 48.9,40.64 42.42,40.64 42.42,38.48 44.83,38.48 45.47,39.12
UNNAMED_2_ADLT8640SA_I41_VIN1 on BOTTOM: 11.94,35.94 11.94,41.02 11.43,41.02 11.43,44.07 11.94,44.07 11.94,46.35 15.24,46.35 15.24,40.01 16,40.01 16,36.07 15.24,36.07 15.24,35.94
UNNAMED_2_ADLT8640SA_I41_VIN1 on BOTTOM: 16.38,35.94 16.38,36.07 15.62,36.07 15.62,40.01 16.38,40.01 16.38,44.45 20.95,44.45 20.95,35.94
UNNAMED_2_ADLT8640SA_I41_VIN1 on BOTTOM: 2.54,44.07 2.54,35.69 6.48,31.75 6.48,30.35 7.49,30.35 7.49,31.75 11.43,35.69 11.43,41.02 11.94,41.02 11.94,44.07 11.43,44.07 11.43,44.32 8.76,44.32 8.51,44.07
UNNAMED_2_ADLT8640SA_I41_VIN1 on LAYER_3: 19.05,41.34 46.04,41.34 46.86,42.16 53.59,42.16 54.48,41.27 56.9,41.27 56.9,39.12 53.09,39.12 52.32,39.88 48.64,39.88 47.82,39.05 44.58,39.05 42.23,36.7 19.05,36.7
UNNAMED_2_CN8PODDEVEN_I14_N5 on TOP: 53.47,37.85 53.47,37.66 54.17,36.96 55.24,36.96 55.24,37.72 54.04,37.72 53.91,37.85
UNNAMED_2_CNBNC5P_I96_CNTR on BOTTOM: 68.96,42.16 68.96,39.5 73.66,39.5 74.55,38.61 74.55,33.91 76.58,33.91 76.58,38.73 77.34,39.5 78.61,39.5 78.61,42.16
UNNAMED_2_CNTP1P_I81_N1 on BOTTOM: 83.19,42.16 83.19,37.59 82.04,37.59 82.04,39.5 81.41,39.5 81.41,42.16
UNNAMED_2_RES_I25_N2 on TOP: 6.22,23.11 6.22,22.1 3.94,22.1 3.94,23.37 4.95,23.37 5.21,23.11
VOUT on TOP: 42.8,52.2 42.8,44.83 57.15,44.83 57.15,52.2
VOUT on TOP: 95.5,43.69 95.5,42.55 94.11,42.55 94.11,43.69
VOUT on TOP: 72.52,4.57 72.52,5.84 72.64,5.97 73.66,5.97 73.66,4.57
VOUT on TOP: 56.77,33.15 56.77,34.16 55.5,34.16 55.5,33.15
VOUT on TOP: 95.12,53.47 95.12,44.32 82.55,44.32 82.55,53.47
VOUT on BOTTOM: 74.17,50.55 74.17,45.59 77.09,45.59 77.09,44.07 82.93,44.07 82.93,50.55
VOUT on BOTTOM: 57.02,37.08 56.9,36.96 56.9,35.69 58.17,35.69 58.17,37.08
VOUT on BOTTOM: 95,53.46 99.56,48.9 98.4,45.84 95.5,44.32 95.5,42.55 94.11,42.55 94.11,43.43 94.49,43.43 94.49,44.32 91.59,45.84 90.43,48.9
VOUT on LAYER_3: 94.61,45.59 42.93,45.59 42.93,52.45 94.61,52.45

Small or netless copper shapes (teardrops, artwork), in the pictures only: 13 on LAYER_3, 3 on TOP, 14 on BOTTOM

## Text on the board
User.Comments: JP1: INSTALL SHUNT ACROSS PINS 3-4
Ref Des/Assembly Top: 8 | 6 | 4 | 2 | 7 | 5 | 3
Ref Des/Silkscreen Top: * | SEE USER GUIDE | 42V,6A MICROPOWER SYNCHRONOUS | STEP-DOWN SILENT SWITCHER 2 | EVAL-LT8640SA-AZ | LT8640SA
DIMENSION: FAB NOTES REVISION: 2ND NOVEMBER 2022 | 8.   IMPEDANCE REQUIREMENTS: IF NO STACKUP IS DEFINED, THE VENDOR IS ALLOWED TO ADJUST THE DIELECTRIC | 13.  PLATING SPECIFICATION: | 9.   FILLET OPTIONS TO ENHANCE RELIABILITY AT PAD JUNCTIONS WHERE SPACING PERMITS. | 10.  THIEVING: | 11.  LAYER TO LAYER REGISTRATION SHALL BE WITHIN 0.003 INCHES. | 12.  DRILL SIZES ARE FINISHED HOLE SIZES. ALL HOLES SHALL BE LOCATED WITHIN 0.005 INCHES DTP,UNLESS SPECIFIED. | 14.  SURFACE FINISH: | 15.  SOLDERMASK: | 1.   DIMENSIONS ARE IN INCHES (EXCEPT WHERE NOTED). | ALL DOCUMENTS & SPECIFICATIONS REFERRED TO BELOW SHOULD BE THE LATEST REVISIONS. | 2.  BOARD MATERIAL:(USE CHECKED ITEMS) | 3.   ALL LAMINATES & BONDING MATERIALS SHOULD BE SELECTED FROM IPC-4101 OR IPC-4103,(TG>170 DEGC TD>300 DEGC) | 4.   REFER TO IPC-6010 SERIES, CLASS 2 FOR FABRICATION. | 5.   REFER TO LAMINATION DIAGRAM FOR OVERALL BOARD THICKNESS, TOLERANCE APPLIES AFTER ALL LAMINATION AND PLATING | 6.   BOW & TWIST NOT TO EXCEED 0.0075 INCHES (0.75%) PER LINEAR INCH AND SHOULD BE MEASURED PER IPC-TM-650, METHOD 2.4.22. | 7.   ACCEPTABILITY PER ADI SPECIFICATION TST00115. | 16.  APPLY SILKSCREEN TO BOTH SIDES USING A NON-CONDUCTIVE, EPOXY BASED INK PER ARTWORK. | ( ) FILLETS ALLOWED | (X) FILLETS NOT ALLOWED | ( ) VENDOR MAY ADD THIEVING TO COMPENSATE FOR LOW COPPER DENSITY AREAS MAINTAINING A MINIMUM | (X) VENDOR MAY NOT ADD THIEVING TO COMPENSATE FOR LOW COPPER DENSITY AREAS. | (X) LPI | ( ) OTHER_________ | COLOR | (X) GREEN | (X) WHITE | ( ) OTHER | HINDER PROPER SOLDER WICKING. BARREL RELIEF ON SOLDERMASK ALLOWED IN UNFILLED VIA IN PAD HOLES. | (X) REFER TO LAMINATION DIAGRAM FOR FINISHED COPPER WEIGHT/THICKNESS REQUIRMENTS | (X) IMMERSION GOLD (ENIG) 1.58-3.94 MICRO INCHES OVER 118-236 MICRO INCHES MIN. OF ELECTROLESS NICKEL PER IPC-4552 | ( ) OSP (ORGANIC SOLDERABILITY PRESERVATIVE) | ( ) IMMERSION SILVER | ( ) SOFT WIRE BONDABLE GOLD 30-50 MICRO INCHES OF SOFT WIRE | ( ) EDGE CONNECTOR FINGERS ARE TO BE PLATED WITH 100 MICRO-INCHES(.0001") OF LOW STRESS | THICKNESS & TRACE WIDTHS TO MEET THE IMPEDANCE REQUIREMENT. IF SPECIFIED, THE VENDOR MUST | TRACE WIDTH & SPACING THAT IMPACT THE REQUIREMENTS MUST HAVE WRITTEN APPROVAL FROM ADI. | MINIMUM BARREL PLATING OF 0.001 INCHES. PLATED HOLES SHALL NOT BE ROUGH OR IRREGULAR SO AS TO | SOLDERMASK OVER BARE COPPER OR BARE GOLD (BOTH SIDES) TO MEET IPC-SM-840. | IF PRESENT,DO NOT MODIFY SOLDERMASK DEFINED PADS (MASK OPENINGS LESS THAN COPPER PAD) WITHOUT APPROVAL. | MEET THE REQUIREMENTS LISTED IN THE IMPEDANCE TABLE. ANY ADJUSTMENT MADE TO THE DEFINED STACKUP, | PROCESSES. FINISHED THICKNESS MEASURED FROM TOP COPPER TO BOTTOM COPPER. | (X)  ISOLA 370HR OR S1000-2 OR IT180 OR EQUIVALENT | ( )  ISOLA-FR408HR OR EQUIVALENT | ( )  ISOLA IS410 | ( )  MEGTRON 6 | ( )  NELCO-4000-13 | ( )  ROGERS 4350B | ( ) ROGERS 3003 | ( ) ARLON 85N | ( ) EM370D | ( )  OTHER ________________________ | UL FLAMMABILITY RATING 94V-0. BOARD MATERIAL & CONSTRUCTION SHALL MEET THE REQUIREMENTS OF UL796/UL796F. | BONDABLE GOLD OVER 100-150 MICRO INCHES OF NICKEL | NICKEL UNDER 30 MICRO-INCHES (.0003') OF GOLD | 0.100 INCH CLEARANCE FROM ALL COPPER FEATURES, | THE STARTING COPPER WEIGHT/THICKNESS CAN VARY AS LONG AS THE FINISHED COPPER | WEIGHT/THICKNESS IS NOT LESS THAN THE SPECIFIED VALUE. | UNLESS OTHERWISE SPECIFIED | HOMOGENOUS MATERIALS IN THIS BOARD SHALL BE COMPLAINT WITH THE EU DIRECTIVE 2002/95/EC | WORKMANSHIP SHALL CONFORM TO IPC-A-600, CLASS 2. | 21.  INTENTIONAL SHORTS: | 17.  FINAL ELECTRICAL TEST TO BE PERFORMED USING PROVIDED IPC-D-356A NETLIST OR ODB++ FORMAT FILE. | 22.  PEMNUTS: | 23.  MANUFACTURER TO ETCH/STAMP WITH PERMANENT NON-CONDUCTIVE INK | ON SECONDARY SIDE UNLESS OTHERWISE SPECIFIED: | 18.  A TIME DOMAIN REFLECTOMETER REPORT (TDR) FOR EACH IMPEDANCE CONTROLLED LAYER & A CERTIFICATE | 19.  IF PRESENT, ALL BLIND/BURIED VIAS WITH AN ASPECT RATIO <1:1 TO BE PLATED SHUT WITH COPPER WHEN | 20.  FOR VIA FILL INFORMATION REFER TO DRILL CHART: | 25. PANELIZATION: | 27.  MINIMUM DESIGN LINE WIDTH IS .006 INCH. | 28.  MINIMUM DESIGN LINE SPACING IS .006 INCH. | IS ACCEPTABLE, ALL OTHER INSTANCES MUST BE REPORTED. | IF AN INTENTIONAL SHORT REPORT IS SUPPLIED AND DOES NOT MATCH THE FAB DATA THEN | THE PCB SHALL HAVE A VERIFICATION STAMP. | ( )  NON-CONDUCTIVE EPOXY FILL ALL 0.XXXX INCHES DRILLED VIAS | ( )  COPPER FILL ALL 0.XXXX INCHES DRILLED VIAS | ( ) PEMNUTS TO BE INSTALLED BY FABRICATOR | ( ) PEMNUTS NOT TO BE INSTALLED BY FABRICATOR | (X) NOT APPLICABLE | USED AS VIA-IN-PAD OR AS A STACKED VIA. BLIND/BURIED VIAS WITH AN ASPECT RATIO >1:1 TO BE FILLED | A. UL CODE-FLAMMABILITY RATING FOR THOSE APPROVED MATERIALS(IF APPLICABLE) | B. DATE CODE | C. LOT NUMBER | D. MANUFACTURER LOGO | BOARDS TO BE SHIPPED IN ARRAY AND KEPT INTACT | PANEL TO BE SUBJECTED TO CUSTOMERS APPROVAL | PANEL SOLDER PASTE STENCIL GERBER TO BE PROVIDED TO ANALOG | CAN'T BE PERFORMED BECAUSE THE TRACE LENGTH IS TOO SHORT ON THE OUTER LAYERS AT THE PIN ESCAPES | ADI APPROVAL IS REQUIRED. | OF COMPLIANCE SHALL BE PROVIDED BY VENDOR AT TIME OF SHIPMENT. INSTANCES WHERE TDR TESTING | WITH NON-CONDUCTIVE EPOXY. | TOOLING: | FINISH: | NOTES: | MATERIAL: | TESTING: | MISCELLANEOUS: | "0"
User.24: SUPPLY | POWER | IN | OUT | I | V | LOAD | A | - | +
User.45: (C14 DNI) | FIGURE | SIZE | 6.0 | 10.0 | 35.0 | 50.0 | 60.0 | 100.0 | 213.0 | 187.0 | PLATED | NON-PLATED | DRILL CHART: TOP to BOTTOM | ALL UNITS ARE IN MILS | QTY | 14 | 632 | 8 | 2 | 12 | 4 | TOLERANCE/NOTES
